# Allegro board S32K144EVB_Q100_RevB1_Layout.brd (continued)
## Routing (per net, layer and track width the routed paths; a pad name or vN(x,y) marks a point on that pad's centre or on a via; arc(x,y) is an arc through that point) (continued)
SDA_SWD_OE_B: length 19.5
  TOP w0.16: v1(25.27,37.82) 24.3,37.82 23.87,37.39 21.49,37.39 U8.20 ; v1(35.85,40.73) 35.59,41 35.59,41.44 R32.2
  BOTTOM w0.16: v1(25.27,37.82) 26.89,36.19 32.87,36.19 35.42,38.74 35.42,40.3 v1(35.85,40.73)
SDA_SWD_OE_B_R: length 3.5
  TOP w0.16: U9.3 35.64,40 35.79,40.15 R39.1 R32.1 v1(36.6,42.23)
SDA_SWD_OE_R: length 3.7
  TOP w0.16: U7.5 R30.2 R31.1 33.03,41.16 R35.2
SDA_USB_CONN_DN: length 13.3
  TOP w0.145: J7.2 4.65,43.37 4.83,43.55 7.56,43.55 7.94,43.17 7.94,43.11 ; 7.94,43.11 8.34,43.52 12.57,43.52 13.41,44.37 15.33,44.37 15.73,43.97 R25.1 ; 7.94,43.11 D19.2
SDA_USB_CONN_DP: length 13.6
  TOP w0.145: 7.92,44.3 7.92,44.29 8.39,43.82 12.44,43.82 13.29,44.66 15.45,44.66 15.94,44.18 R21.1 ; 7.92,44.3 7.46,43.85 4.85,43.85 4.67,44.02 J7.3 ; 7.92,44.3 D18.2
SDA_USB_DN: length 2.1
  TOP w0.145: U8.4 17.65,41.94 17.65,42.08 17.08,42.65 R25.2
SDA_USB_DP: length 2.1
  TOP w0.145: R21.2 17.25,42.9 17.29,42.86 17.29,42.86 17.84,42.31 17.99,42.31 U8.3
SDA_USB_P5V_SENSE: length 4.6
  TOP w0.16: U8.30 21.47,42.72 R20.1 22.79,44.04 22.79,44.04 R14.2 v1(23.98,45.22)
SDA_USBSHIELD: length 9.3
  TOP w0.16: 5.62,40.27 L2.1 6.21,40.76
  TOP w1.016: J7.9 J7.8 J7.10
SDA_VOUT33: length 6.4
  TOP w0.254: U8.5 16.91,41.97 15.71,41.97 C9.1
  TOP w0.508: J9.2 15.18,41.44 C9.1
SDA_XTAL: length 5.3
  TOP w0.16: Y1.1 23.41,35.3 23.41,35.71 C20.1 22.61,36.51 20.95,36.51 U8.18
SW1_RST_B: length 13.5
  TOP w0.16: SW5.4 SW5.2 11.15,53.63 v1(10.7,53.19) C1.1
  L3_MIX w0.16: v1(10.7,53.19) 10.7,51.72 11.65,50.77 11.65,49.19 J104.2
SWD_CLK_TGTMCU_BUF: length 21.8
  TOP w0.16: U10.4 29.91,37.62 v1(30.07,37.47) ; J8.1 42.68,43.86 v1(42.68,40.06)
  BOTTOM w0.16: v1(30.07,37.47) 32.95,37.47 34.74,39.26 34.74,40.32 35.61,41.19 37.17,41.19 38.3,40.06 v1(42.68,40.06)
SWD_DIO_TGTMCU_BUF: length 23.9
  TOP w0.16: U7.4 v1(30.02,40.66) ; U2.2 v1(30.44,47.35) 33.08,47.35 35.6,44.83 39.23,44.83 41.33,42.73 J106.1
  BOTTOM w0.16: v1(30.02,40.66) 30.78,40.66 32.05,41.94 32.05,45.74 v1(30.44,47.35)
TC_EXTAL_TP: length 2.2
  TOP w0.16: U8.10 16.39,38.34 16.09,38.34 15.72,37.97 TP11.1
TC_SDA_USB_ID_TP: length 2.2
  TOP w0.16: J7.4 5.88,44.67 TP6.1
TC_XTAL_TP: length 3
  TOP w0.16: TP10.1 15.83,38.85 16.19,38.85 U8.9
TP_2102_A: length 1.6
  TOP w0.16: U1.3 v1(7.74,53.46)
TP_2102_B: length 1.2
  TOP w0.16: U1.6 6.55,50.61 v1(6.24,50.29)
UART1_RX_TGTMCU_BUF: length 7
  TOP w0.16: U4.4 30.29,43.94 30.66,43.57 v1(32.75,43.57) 35.45,43.57 R24.1
UART1_RX_TGTMCU_R: length 8.8
  TOP w0.16: U8.25 22.89,40.6 23.67,40.6 23.88,40.39 25.35,40.39 v1(25.86,40.9) ; v1(27.02,43.73) 27.83,43.73 28.04,43.94 U4.3
  BOTTOM w0.16: v1(27.02,43.73) 27.02,42.06 v1(25.86,40.9)
UART1_TX_TGTMCU_BUF: length 6.4
  TOP w0.16: U2.1 v1(31.84,46.83) 32.26,46.83 R18.1
UART1_TX_TGTMCU_R: length 10.9
  TOP w0.16: U8.24 v1(23.29,40.08) ; v1(27.12,44.65) 27.65,45.18 27.65,47.12 27.88,47.35 U2.6
  BOTTOM w0.16: v1(23.29,40.08) 26.34,43.14 26.34,43.87 v1(27.12,44.65)
UART_RX: length 59
  TOP w0.16: R24.2 v1(34.07,43.05) ; R161.2 v1(84.66,44.35)
  BOTTOM w0.16: v1(34.07,43.05) 35.69,44.67 38.34,44.67 38.81,44.2 44.26,44.2 51.04,37.42 53.5,37.42 53.82,37.74 54.65,37.75 54.66,37.75 56.12,37.75 60.68,42.31 82.63,42.31 v1(84.66,44.35)
UART_TX: length 57.5
  TOP w0.16: v1(86.33,44.28) 86.33,43.34 R162.2 ; R18.2 v1(36.98,44.16)
  BOTTOM w0.16: v1(86.33,44.28) 83.79,41.74 67.09,41.74 66.65,41.29 66.22,41.29 65.86,41.65 60.5,41.65 56.26,37.42 54.8,37.42 54.8,37.41 53.96,37.4 53.64,37.08 50.42,37.08 43.94,43.56 37.58,43.56 v1(36.98,44.16)
V_TGTMCU: length 14.7
  TOP w0.254: 2.98,50.98 R2.2 2.47,50.47 ; U1.8 8.14,50 v1(8.55,49.59) ; U2.8 29.05,46.31 v1(29.34,46.01) U4.6 ; v1(30.05,38.7) 29.88,38.7 29.8,38.62 U10.6 ; 3.5,51.1 R4.1 2.99,50.59 ; 2.99,49.63 C4.1 ; U7.6 29.81,41.66 v1(30.04,41.89) ; C8.1 v1(30.09,42.77) ; 1.49,50.47 C2.1 0.98,50.98
  TOP w0.762: v1(38.48,42.57) v1(39.52,42.57) 39.52,39.41 38.86,38.76 SH1.1
  vias: v1(1.85,50.09) v1(2.77,50.09)
VREFH: length 16.2
  TOP w0.279: R99.2 63.08,31.47 64.89,29.66 U17.12
  TOP w0.508: R103.2 58.19,31.47 R99.2
  TOP w0.635: R109.1 D7.C 55.67,32.45 55.9,32.23 C148.1 v1(57.06,31.46) R103.2
VSUP: length 55.1
  TOP w0.254: U19.14 v1(15.66,18.74)
  TOP w0.381: Q1.3 32.88,18.84 ; Q1.3 32.88,18.44 ; Q1.3 32.88,18.24 ; Q1.3 32.08,18.14 ; Q1.3 31.68,18.19 ; Q1.3 32.88,18.64 ; C29.1 28.68,13.52 ; C29.1 27.72,13.14 ; C29.1 28.68,13.9 ; C29.1 28.04,13.14 ; C29.1 28.68,13.14 ; C29.1 28.68,14.29 ; D13.C 43.68,10.01 ; D13.C 42.08,11.61 ; D13.C 42.08,10.01 ; D13.C 42.88,10.01 ; D13.C 42.08,10.81 ; D13.C 43.68,11.61 ; D13.C 43.68,10.81 ; D13.C 42.88,11.61 ; Q1.2 32.08,17.86 ; Q1.2 32.88,17.37 ; Q1.2 32.88,17.77 ; Q1.2 32.08,16.87 ; Q1.2 31.68,16.92 ; Q1.2 32.88,16.97 ; D9.C 29.28,11.62 ; D9.C 27.68,12.42 ; D9.C 28.48,10.82 ; D9.C 29.28,12.42 ; D9.C 29.28,10.82 ; D9.C 28.48,12.42 ; D9.C 27.68,11.62 ; D9.C 27.68,10.82 ; 42.23,12.33 C128.1 ; C128.1 42.23,13.28 ; C128.1 42.87,12.33 ; C128.1 42.55,12.33 ; C128.1 42.23,14.23 ; C128.1 42.87,14.23 ; 34.92,17.78 C47.1 ; C47.1 35.68,18.42 ; C47.1 34.15,18.42 ; C47.1 34.15,17.78 ; C47.1 35.68,17.78 ; C47.1 34.54,17.78 ; 31.34,11.82 TP36.1 ; TP36.1 31.44,12.29 ; TP36.1 31.91,11.25 ; TP36.1 32.48,11.82 ; TP36.1 31.44,11.35 ; TP36.1 32.38,11.35 ; 31.68,15.65 Q1.1 ; Q1.1 32.08,15.6 ; Q1.1 32.88,16.5 ; Q1.1 32.88,15.7 ; Q1.1 32.08,16.59 ; Q1.1 32.88,16.1
  TOP w0.61: D6.A 20.63,23.5 21.29,24.16 U21.7
  TOP w0.635: v1(11.06,9.95) 11.06,9.67 10.42,9.04 R537.1 ; D6.A v3(17.99,23.5)
  vias: v1(28.11,12.79) v1(29.07,14.31) v1(29.09,13.6) v1(29.01,12.77)
VTRG_EN: length 4.6
  TOP w0.16: U11.3 v1(9.98,31.94) R70.2 R68.1 R69.2
VTRG_FAULT_B: length 16.3
  TOP w0.16: v1(20.38,43.64) 20.38,43.04 U8.32 ; v1(12.67,35.53) R60.2 11.22,35.53 U11.4
  BOTTOM w0.16: v1(12.67,35.53) 14.62,37.48 14.62,39.3 15.71,40.39 17.59,40.39 20.38,43.18 v1(20.38,43.64)
N20335552: length 5
  TOP w0.16: R119.1 47.85,42.36 48.38,41.83 J14.6
N20335572: length 2.5
  TOP w0.16: J14.8 R120.1
N20337946: length 53
  TOP w0.16: R166.2 73.48,14.93 v1(74.22,14.19) ; R165.2 v1(82.99,44.37)
  L3_MIX w0.16: v1(83.83,14.27) 83.83,17.51 83.36,17.97 83.36,35.15 82.66,35.86 82.66,44.05 v1(82.99,44.37) ; v1(74.22,14.19) 74.22,12.77 74.47,12.52 74.47,9.81 74.35,9.68 74.35,6.93 J5.3
  BOTTOM w0.16: v1(83.83,14.27) 83.26,14.84 74.88,14.84 v1(74.22,14.19)
N20338949: length 55.1
  TOP w0.16: R168.2 71.69,13.97 v1(71.22,13.5) ; R167.2 v1(81.31,44.27) ; J5.1 v1(71.69,5.12)
  L3_MIX w0.16: v1(71.22,13.5) 71.61,13.1 71.61,6.5 71.69,6.43 v1(71.69,5.12) ; v1(81.31,44.27) 81.92,43.66 81.92,35.2 82.32,34.8 82.32,18.13 82.16,17.98 v1(82.16,14.16)
  BOTTOM w0.16: v1(82.16,14.16) 81.83,14.48 76.37,14.48 75.61,13.72 71.91,13.72 71.68,13.5 v1(71.22,13.5)
N20340793: length 25.3
  TOP w0.16: SH13.1 95.15,32.61 95.43,32.9 v1(95.89,32.9)
  L3_MIX w0.16: J6.3 90.41,51.83 90.41,47.53 94.2,43.73 94.2,40.26 96.22,38.24 96.22,33.22 v1(95.89,32.9)
N20341657: length 96.4
  TOP w0.16: R133.1 88.69,16.31 v1(89.52,15.47) ; v1(66.52,13.96) R132.1
  L3_MIX w0.16: J1.13 48.22,48.78 48.73,48.27 48.73,28.39 45.85,25.51 45.85,23.58 46.98,22.45 46.98,17.73 45.95,16.7 45.95,9.17 v1(47.71,7.41)
  BOTTOM w0.16: v1(47.71,7.41) 49.41,9.11 54.05,9.11 54.61,9.66 54.9,9.66 59.2,13.96 v1(66.52,13.96) 70.79,13.96 72.3,15.47 v1(89.52,15.47)
N20341806: length 99.6
  TOP w0.16: R135.1 v1(62.15,13.37) ; v1(88.69,13.75) R134.1
  L3_MIX w0.16: v1(47.17,5.91) 47.17,6.91 44.79,9.29 44.79,14.56 44.67,14.69 44.67,16.29 45.76,17.39 45.76,23.19 45.51,23.44 45.51,25.65 46.29,26.42 46.29,29.03 46.2,29.12 46.2,30.53 48.36,32.68 48.36,48.16 47.47,49.05 47.47,51.59 J1.15
  BOTTOM w0.16: v1(47.17,5.91) 47.17,6.03 49.82,8.68 54.1,8.68 54.75,9.32 56.12,9.32 60.16,13.37 v1(62.15,13.37) 70.22,13.37 70.8,12.78 78.69,12.78 78.93,12.53 82.47,12.53 82.75,12.82 85.16,12.82 86.12,13.78 87.37,13.78 87.4,13.75 v1(88.69,13.75)
N20342040: length 84.1
  TOP w0.16: v1(28.92,50.71) 29.38,50.71 29.53,50.56 31.46,50.56 32.68,50.56 32.68,50.56 33.01,50.56 33.27,50.3 33.86,49.7 39.24,49.7 40.29,48.66 55.61,48.66 56.67,47.6 75.08,47.6 76.78,45.9 87.52,45.9 87.57,45.85 88.26,45.85 88.88,45.23 91.45,45.23 94.86,41.82 R567.1 94.86,40.55 94.85,40.54 R539.1
  BOTTOM w0.16: v1(28.92,50.71) 28.92,50.19 28.47,49.74 22.39,49.74 J2.19
N20342083: length 76.7
  TOP w0.16: v1(28.28,50.2) 32.85,50.2 33.69,49.36 39.1,49.36 40.17,48.3 55.46,48.3 56.5,47.26 74.91,47.26 76.61,45.57 86.59,45.57 86.64,45.51 87.84,45.51 90.22,43.12 90.22,41.83 90.16,41.76 R568.1 R540.1
  BOTTOM w0.16: J2.17 24.47,50.2 v1(28.28,50.2)
N20344687: length 67
  TOP w0.16: R146.1 77.18,14.31 76.12,13.25 v1(74.81,13.25) ; v1(93.32,37.24) R543.2 94.1,38.19 94.11,38.18 R541.2
  L3_MIX w0.16: v1(74.81,13.25) 74.81,12.66 74.81,12.66 74.81,9.67 74.81,9.66 v1(74.81,8.85) ; v1(93.32,37.24) 93.32,31.91 93.51,31.73 93.51,31.35 93.23,31.07 93.23,26.88 92.64,26.3 92.64,22.84 92.61,22.81 92.61,13.42 v1(92.73,13.29)
  BOTTOM w0.16: J4.11 64.31,5.97 64.31,6.32 66.84,8.85 70.04,8.85 70.1,8.91 70.74,8.91 70.81,8.85 v1(74.81,8.85) ; v1(92.73,13.29) 89.8,13.29 88.88,14.21 86.08,14.21 85.02,13.15 82.61,13.15 82.33,12.87 79.07,12.87 78.7,13.25 v1(74.81,13.25)
N20344693: length 67.5
  TOP w0.16: R147.1 88.69,23.01 89.15,22.55 89.27,22.55 90.36,21.46 v1(91.15,21.46) ; v1(90.09,36.98) R542.2 88.7,38.18 R544.2 ; J4.9 61.86,6.06 62.08,6.06 63.22,7.21 65.54,7.21 68.45,10.12 71.39,10.12 73.15,8.36 76.94,8.36 77.36,8.78 77.56,8.78 78.88,10.1 82.75,10.1 83.64,9.21 88.7,9.21 v1(91.15,11.67)
  L3_MIX w0.16: v1(91.15,11.67) v1(91.15,21.46) 90.82,21.79 90.82,21.83 90.69,21.96 90.69,22.66 90.14,23.22 90.14,24.52 90.23,24.61 90.23,28.54 89.7,29.07 89.7,35.24 90.51,36.06 90.51,36.42 90.09,36.84 v1(90.09,36.98)
N20408163: length 2.3
  TOP w0.16: U15.3 R170.2 34.12,32.71 R169.2
N20408770: length 1.6
  TOP w0.16: U15.4 40.06,32.71 40.06,32.71 C59.1
N20447644: length 70.3
  TOP w0.16: SH11.2 v1(94.4,36.71)
  L3_MIX w0.16: v1(62.14,26.25) 62.14,50.48 63.46,51.8 J1.1 ; v1(93.82,27.84) 93.82,30.25 94.18,30.61 94.18,32.01 94.08,32.11 94.08,36.38 v1(94.4,36.71)
  BOTTOM w0.16: v1(93.82,27.84) 76.86,27.84 75.58,26.56 64.27,26.56 64.25,26.57 62.46,26.57 v1(62.14,26.25)
N20447648: length 66.9
  TOP w0.16: v1(95.62,34.18) 95.16,34.18 95.15,34.19 SH12.2
  L3_MIX w0.16: v1(59.29,29.79) 59.29,51.75 J1.3 ; v1(95.62,34.18) 95.46,34.03 95.45,34.03 95.18,33.76 95.18,33.75 94.7,33.27 94.7,30.15 94.51,29.96 v1(94.51,29.5)
  BOTTOM w0.16: v1(94.51,29.5) 93.7,30.31 90.84,30.31 90.7,30.45 88.89,30.45 88.13,29.69 86.69,29.69 86.23,30.15 77.23,30.15 77.22,30.14 71.08,30.14 70.73,29.79 v1(59.29,29.79)
N20483325: length 50.2
  TOP w0.16: R81.1 60.01,25.42 58.68,24.09 52.06,24.09 v1(51.73,23.77)
  L3_MIX w0.16: v1(51.73,23.77) 50.81,22.84 50.81,18.13 51.24,17.69 51.28,17.69 52.2,16.77 52.2,16.39 50.26,14.44 v1(48.67,14.44)
  BOTTOM w0.16: J3.2 29.18,3.86 29.18,6.43 30.27,7.52 33.5,7.52 37.64,11.65 45.88,11.65 v1(48.67,14.44)
N20483330: length 48.3
  TOP w0.16: R90.1 v1(59.87,30.38)
  L3_MIX w0.16: v1(59.87,30.38) 59.87,24.57 55.76,20.47 v1(55.76,18.51)
  BOTTOM w0.16: v1(55.76,18.51) 54.17,18.51 52.41,16.75 52.41,16.37 51.42,15.38 50.83,15.38 46.16,10.71 37.61,10.71 33.45,6.55 32.64,6.55 31.71,5.62 31.71,3.85 J3.4
N20483362: length 70.4
  TOP w0.16: R545.1 v1(75.02,44.28)
  L3_MIX w0.16: v1(75.02,44.28) 73.91,43.17 73.91,38.89 73.41,38.39 73.41,38.01 75,36.42 75,34.98 74.17,34.15 74.17,19.21 73.44,18.48 73.44,18.06 73.49,18 73.49,12.77 v1(74.01,12.26)
  BOTTOM w0.16: v1(74.01,12.26) 64.85,12.26 61.78,9.19 59.46,9.19 58.61,8.34 49.96,8.34 47.63,6.02 47.63,5.38 46.05,3.79 44.35,3.79 J3.14
N20483368: length 57.5
  TOP w0.16: R546.1 v1(65.24,44.28)
  L3_MIX w0.16: v1(65.24,44.28) 65.24,35.71 63.48,33.95 63.48,16.59 63.94,16.14 63.94,11.34 61.15,8.55 v1(60.3,8.55)
  BOTTOM w0.16: J3.16 47.47,4.36 47.98,4.36 48.38,4.77 48.38,6.17 49.55,7.34 59.09,7.34 v1(60.3,8.55)
N20487643: length 4.3
  TOP w0.16: R533.2 C533.1 ; R533.2 v1(99.2,30.39) ; R533.2 R525.1
N20487701: length 2.6
  TOP w0.16: R527.1 SW8.1
N20487722: length 4.4
  TOP w0.16: v1(98.17,17.25) C535.1 R534.2 R528.1
N20498073: length 20.6
  TOP w0.16: Q1.4 v1(32.08,20.66) ; v1(14.9,18.24) U19.15
  BOTTOM w0.16: v1(32.08,20.66) 21.16,20.66 20.76,20.26 19.95,20.26 18.55,18.86 18,18.86 17.38,18.24 v1(14.9,18.24)
N20501046: length 23
  TOP w0.16: v1(9.65,12.44) R537.2 SW9.1 SW9.3 ; U19.12 v1(15.66,19.74)
  L3_MIX w0.16: v1(9.65,12.44) 9.65,12.9 9.74,12.99 9.74,19.34 10.25,19.85 15.09,19.85 15.2,19.74 v1(15.66,19.74)
N20514938: length 32.3
  TOP w0.203: 21.39,18.24 U19.6
  TOP w0.356: 21.39,18.24 22.14,18.98 R535.2
  TOP w0.381: R535.2 24.98,18.98 ; R535.2 24.98,19.62 ; R535.2 24.03,19.62 ; R535.2 23.08,19.62
  TOP w0.635: 25.46,18 Q1.5 ; Q1.5 28.05,15.62 ; Q1.5 25.46,20.38 ; Q1.5 28.05,20.39 ; Q1.5 30.64,20.38 ; Q1.5 30.64,15.63 ; Q1.5 30.64,18 ; Q1.5 25.46,15.63
  vias: v1(30.75,21.68)
N20519466: length 4.4
  TOP w0.16: C536.1 13.63,21.12 v1(14.21,20.54) 15.51,19.24 U19.13
N20529258: length 4.2
  TOP w0.61: R80.2 R171.2 D6.C
N20533540: length 2.6
  TOP w0.16: R172.1 SW7.1
N20579312: length 15.6
  TOP w0.508: v1(7.96,13.25) 7.96,14.26 C40.1 ; 7.96,24.04 v1(6.57,24.04)
  BOTTOM w0.508: v1(7.96,13.25) 7.96,22.64 v1(6.57,24.04)
N20579404: length 3.9
  TOP w0.305: R92.2 8.34,17.31 8.9,16.75 9.54,16.75 J109.2
N20579447: length 4.6
  TOP w0.305: J108.2 11.01,19.75 9.77,20.99 R98.2
N20615890: length 3.5
  TOP w0.16: R556.1 39.49,22.39 39.66,22.56 39.66,22.9 39.66,23.28 39.66,23.29 39.66,24.26 39.5,24.42 U26.5
N20616554: length 3.4
  TOP w0.16: R558.1 46.33,22.39 46.77,22.83 46.77,24.26 46.61,24.42 U28.5
N20618570: length 3.5
  TOP w0.16: R559.2 51.49,25.69 51.65,25.53 51.65,24.42 51.38,24.15 U29.5
N20622415: length 3.4
  TOP w0.16: R560.1 42.82,22.39 43.23,22.8 43.23,24.28 43.07,24.44 U30.5
N20627960: length 1.4
  TOP w0.16: R562.1 46.83,19.3 46.57,19.3 46.32,19.05 U32.5
N20628442: length 1.4
  TOP w0.16: R563.1 45.19,20.96 45.31,20.83 U32.7
N20629363: length 3.1
  TOP w0.16: U33.5 51.42,17.82 51.73,18.13 51.73,18.62 51.57,18.78 51.32,18.78 R564.2
N20629726: length 1.6
  TOP w0.16: U32.2 44.91,17.64 44.42,17.15 R565.2
N20631005: length 1.4
  TOP w0.16: U33.3 50.13,16.94 R566.2

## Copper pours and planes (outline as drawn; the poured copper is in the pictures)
GND on BOTTOM: 125.25,8.89 122.79,2.96 116.87,0.51 8.93,0.52 3,2.98 0.55,8.9 0.52,49.52 2.96,55.45 8.89,57.91 116.87,57.91 122.79,55.46 125.25,49.53 ; 51 cut-outs
P3V3 on TOP: 38.97,26.63 38.97,26.65 38.38,27.24 38.38,35.45 45.39,35.45 45.39,26.93 45.09,26.63
P3V3 on L3_MIX: 41.21,32.39 41.21,28.41 39.64,26.83 39.64,24.83 37.95,23.13 37.95,7.56 36.8,6.42 36.8,4.03 32.57,4.03 32.57,23.74
P3V3_SDA on TOP: 8.44,51.41 9.73,51.41 10.09,51.05 10.09,49.5 9.33,49.5 8.44,50.4
P3V3_SDA on TOP: 31.33,37.21 31.33,35.49 31.24,35.39 29.19,35.39 29.01,35.58 29.01,37.25 31.29,37.25
P3V3_SDA on BOTTOM: 29.6,36.74 29.6,37.88 30.45,38.74 33.13,38.74 34.22,39.82 34.22,40.4 35.4,41.58 37.86,41.58 37.86,42.89 34.29,42.89 31.36,39.96 28.92,39.96 28.87,40 28.87,42.35 31.09,42.35 31.38,42.64 31.38,43.4 30.42,44.36 30.42,44.43 30.44,44.44 30.44,45.69 29.03,45.69 26.89,47.83 22.35,47.83 18.16,52.02 7.52,52.02 6.75,52.79 4.78,52.79 4.72,52.73 4.72,51.49 5.95,50.25 9.39,50.25 10.59,49.05 10.59,27.64 11.78,26.45 18.7,26.45 19.42,27.16 19.42,28.39 14.57,28.39 14.57,33.88 16.92,36.23 16.92,38.23 16.44,38.23 16.27,38.06 16.27,36.67 13.58,33.98 13.58,31.39 12.24,31.39 11.86,31.77 11.86,35.72 13.48,37.34 13.48,43.84 14.48,44.84 16.84,44.84 19.22,42.46 19.85,43.08 19.85,44.32 17.24,46.93 17.24,48.9 19.44,48.9 21.68,46.66 24.62,46.66 26.22,45.07 28.25,45.07 28.25,42.82 27.57,42.13 27.57,40.1 27.09,39.62 27.09,38.53 27.28,38.34 28.05,38.34 28.3,38.09 28.3,37.32 28.88,36.74
P5V0 on TOP: 30.35,32.51 32.85,32.51 35,30.37 35,26.8 34.9,26.7 32.42,26.7 30.35,28.77
P5V0 on BOTTOM: 23.85,34.37 28.15,34.37 28.53,33.99 32.74,33.99 33.09,34.33 33.09,34.38 33.96,35.26 42.69,35.26 42.69,26.33 30.47,26.33 30.47,31.07 26.49,31.07 26.49,26.33 23.85,26.33
P5V0 on L3_MIX: 43.47,5.07 42.44,4.04 36.97,4.04 36.97,6.24 38.34,7.62 38.34,23.27 40.2,25.13 40.2,26.76 41.68,28.24 43.47,28.24
P5V_SBC on TOP: 33.22,25.92 33.22,21.45 36.37,21.45 37.02,20.79 41.54,20.79 41.84,21.09 41.84,22.49 40.92,23.42 40.15,23.42 39.5,22.77 37.89,22.77 37.89,25.92
P5V_SBC on BOTTOM: 42.31,20.13 42.31,16.91 44.58,16.91 44.58,19.37 43.91,20.04 43.91,21.15 44.03,21.26 45.57,21.26 46.59,20.25 46.59,19.53 47.69,18.43 49.39,18.43 49.76,18.79 49.76,23.76 49.73,23.76 49.73,24.37 49.2,24.9 48.65,24.9 47.19,23.44 38.5,23.44 38.5,23.51 38.24,23.77 35.89,23.77 35.89,26.14 30.3,26.14 30.3,30.89 26.69,30.89 26.69,22.87 31.94,22.87 33.3,21.5 37.65,21.5 38.22,20.93 41.42,20.93 41.42,20.94 41.5,20.94
P5V_SDA on TOP: 22.29,44.5 23.47,45.69 22.26,46.9 6.97,46.9 6.97,45.62 17.57,45.62 17.93,45.99 19.59,45.99 19.95,45.62 21.17,45.62
P5V_SDA on BOTTOM: 6.91,45.99 6.91,28.58 9.61,28.58 9.61,46.33 7.24,46.33
VBATT on TOP: 21.55,12.74 26.96,12.74 26.96,6.94 26.69,6.67 22.08,6.67 21.55,7.2
VDD on TOP: 45.77,38.45 51.32,38.45 52.51,39.64 54.85,39.64 54.85,38.09 54.84,38.08 54.84,36.22 48.7,36.22 48.7,25.93 45.76,25.93 45.76,35.84 39.81,35.84 39.81,38.45 40.38,39.02 45.2,39.02
VDD on TOP: 35.74,26.64 35.74,30.8 38.19,30.8 38.19,26.64
VDD on BOTTOM: 43.11,30.5 43.11,26.09 36.07,26.09 36.07,24.12 38.33,24.12 38.32,24.11 38.78,23.66 46.69,23.66 47.15,24.11 47.14,24.11 48.17,25.14 49.12,25.14 49.99,24.27 49.99,18.65 49.53,18.19 46.89,18.19 46.32,18.76 46.32,20.14 45.37,21.09 44.24,21.09 44.04,20.89 44.04,20.19 44.78,19.45 44.78,17.2 46.37,15.61 49.35,15.61 51.1,17.36 52.33,17.36 53.7,18.72 55.38,18.72 55.49,18.83 55.49,30.5
VDD on BOTTOM: 70.76,4.08 85.76,4.08 90.48,8.8 108.44,8.8 109.23,8.02 116.65,8.02 118.39,9.76 118.39,16.91 119.63,18.14 119.63,47.87 115.65,51.85 106.57,51.85 103.57,48.85 92,48.85 89.65,51.2 80.04,51.2 80.04,57.03 112.63,57.03 112.64,57.03 118.34,57.03 124.56,50.8 124.56,9.61 115.51,0.56 69.72,0.56 69.72,3.04
VDD on L3_MIX: 71.7,3.86 71.7,0.56 26.38,0.56 25.9,1.05 25.9,8.08 26.05,8.23 26.05,24.67 39.86,38.48 44.34,38.48 44.34,36.08 32.11,23.85 32.11,3.86 ; 1 cut-out
VDD_MCU on TOP: 58.07,41.96 58.07,34.46 56.85,34.46 56.85,32.09 62.99,32.09 65.08,30 68.83,30 69.15,29.68 75.6,29.68 75.6,31.21 69.22,31.21 68.82,30.81 65.75,30.81 64.6,31.97 64.6,33.35 61.36,33.35 59.92,34.78 59.92,41.96
VDD_MCU on L3_MIX: 75.31,42.76 75.31,34.93 74.55,34.18 74.55,19.62 74.88,19.3 74.88,17.74 75.8,17.74 75.8,22.26 75.6,22.46 75.6,33.29 76.25,33.94 76.25,42.76
(no net) on TOP: 8.9,0.52 2.98,2.97 0.53,8.89 0.52,40.98 0.84,40.98 0.84,42.44 0.52,42.44 0.52,45.61 0.84,45.61 0.84,47.07 0.52,47.07 0.52,49.54 2.97,55.46 8.89,57.91 116.87,57.91 122.79,55.46 125.25,49.53 125.25,8.89 122.79,2.96 116.87,0.51 ; 63 cut-outs
(no net) on L3_MIX: 125.25,8.89 122.79,2.96 116.87,0.51 8.9,0.52 2.99,2.98 0.55,8.9 0.52,49.54 2.97,55.46 8.89,57.91 116.87,57.91 122.79,55.46 125.25,49.53 ; 62 cut-outs
SDA_USBSHIELD on TOP (solid shape): 2.43,48.27 5.1,48.27 5.1,46.25 3.86,46.25 3.86,47.25 0.53,47.25 0.53,48.98 2.43,48.98
SDA_USBSHIELD on TOP (solid shape): 5.1,39.78 2.43,39.78 2.43,39.07 0.53,39.07 0.53,40.8 3.86,40.8 3.86,41.8 5.1,41.8
SDA_USBSHIELD on TOP: 5.01,39.78 6.6,39.78 6.6,40.84 6.59,40.85 4.97,40.85 4.93,40.81 4.93,39.86
V_TGTMCU on TOP: 0.83,51.31 3.57,51.31 3.77,51.11 3.77,49.76 3.45,49.43 1.64,49.43 0.83,50.24
V_TGTMCU on L3_MIX: 1.3,51.32 7.24,51.32 9.03,49.52 9.03,47.25 9.97,46.32 12.11,46.32 15.42,49.62 32.42,49.62 35.79,46.26 39.87,46.26 39.87,42.24 38.09,42.24 38.09,43.84 34.98,43.84 30.96,47.86 29.93,47.86 29.93,46.9 31.22,45.61 31.22,41.9 30.35,41.04 30.35,38.27 28.8,38.27 28.8,45.71 27.13,47.39 15.51,47.39 13.28,45.15 8.99,45.15 4.85,49.29 1.3,49.29
VSUP on TOP: 27.59,14.56 31.48,14.56 31.48,19.02 37.47,19.02 37.47,14.66 43.92,14.66 43.92,10.32 43.91,10.32 43.91,9.04 39.7,9.04 39.7,10.31 27.59,10.31
VSUP on BOTTOM: 18.66,24.27 18.66,21.95 16.1,21.95 16.1,18.52 13.8,18.52 13.8,14.56 29.35,14.56 29.35,12 13.33,12 12.39,11.06 12.39,9.6 10.85,9.6 10.73,9.72 10.73,12.4 11.88,13.56 11.88,24.27 ; 1 cut-out
N20514938 on TOP: 30.99,15.3 30.99,21.83 22.24,21.83 22.24,18.48 25.06,18.48 25.06,15.3

Small or netless copper shapes (teardrops, artwork), in the pictures only: 1 on L2_GND

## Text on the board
BOTTOM: 170-29248 REV B1 | 7 OF 10 | SECONDARY SIDE
Board Geometry/Soldermask Bottom: 8 OF 10 | SECONDARY SOLDERMASK
Ref Des/Silkscreen Bottom: GND | LIN | VBAT | CAN_HI | CAN_LO | VDD | E10/A3 | NC | E11/A2 | A14 | AREF | E7 | C13 | B2 | C12 | B3 | E8 | B4 | B5 | D0 | D16 | D14 | B6 | VIN | D15 | D13 | IOREF | B7 | E0 | RESET | 3.3V | E9 | 5V | C5 | C4 | A10 | A4 | E8/C11 | D4 | C7 | E3 | C3/C10 | B12 | D3 | C6 | B0 | B11 | D5 | B17 | B1 | B10 | D12 | B14 | A6/E11/A2 | B9 | D11 | B15 | D10 | C0/E10/A3 | B8 | B16 | E2 | A3 | A17 | C14 | A11 | E6 | A2 | C3 | E4 | A9 | A8 | E5 | E12 | A12 | A13 | D17 | C9 | C8 | E16 | A15/D11 | C16 | D8 | E15 | A16/D10 | C17 | D9 | E14 | A1 | D2 | E13 | A0 | D1 | A7 | B13 | E1 | C1 | D7 | C2 | D6 | C15 | OpenSDA | 9 OF 10 | SECONDARY SILKSCREEN
User.Comments: 1 OF 1 | TEST PROBE | 1/1 | 1
TOP: 4 OF 10 | PRIMARY SIDE
Board Geometry/Soldermask Top: 3 OF 10 | PRIMARY SOLDERMASK
Ref Des/Silkscreen Top: GND | SBC_IO | VSUP | LIN | RESET | # | P5V0 | SBC_SCK | SBC_MISO | SBC_CAN_RX | SBC_MOSI | SBC_CAN_TX | SBC_CS | ## | SWD_CLK | SWD_DIO | VDD | P3V3 | MCU | * | POT | B | G | R | CAN | LO | HI | SDA | PWR IN (5-12V) | SWD | ** | TOUCH ELECTRODES | 2 OF 10 | PRIMARY SILKSCREEN | S32K144EVB-Q100
L2_GND: 5 OF 10 | GROUND PLANE
L3_MIX: 6 OF 10 | MIXED SIGNAL
DIMENSION: PRIMARY DATUM | GRID ORIGIN
BODY_CENTER: 22. | INTENTIONAL SHORT (8) ON: | Location           RefDes      Net 1                     Net 2 | (113.50 1329.90)   J9        P3V3_SDA               &  SDA_VOUT33 | (299.72 1681.10)   J105      SDA_RST_TGTMCU_J_B     &  SDA_RST_TGTMCU_B | (1213.10 1300.30)  SH1       V_TGTMCU               &  VDD | (1278.70 1578.40)  J8        SWD_CLK_TGTMCU_BUF     &  JTAG_TCLK/SWD_CLK | (1278.70 1442.70)  J106      SWD_DIO_TGTMCU_BUF     &  JTAG_TMS/SWD_DIO_PTA4 | (3336.22 1082.50)  SH13      N20340793              &  PTD2 | (3336.70 1202.70)  SH11      PTA2                   &  N20447644 | (3336.71 1144.40)  SH12      PTA3                   &  N20447648 | 17 | X4 | 16 | 8
PASTEMASK_TOP: 1 OF 10 | PASTEMASK TOP
User.5: 10 OF 10 | SECONDARY PASTEMASK
User.14: 09-01-16 | 12-19-16 | O.R. | B | B1 | RE-SPIN PER ECO66785 | CHANGED THE SAMTEC TO JTX
User.20: FIGURE | SIZE | 8.0 | 10.0 | 14.0 | 15.0 | 28.0 | 31.0 | 40.0 | 44.0 | 45.0 | 100.0 | 125.0 | 34.0x26.0 | 60.0x33.0 | 111.0x32.0 | 122.0x32.0 | DRILL CHART: TOP to BOTTOM | ALL UNITS ARE IN MILS | TOLERANCE | +0.0/-8.0 | +0.0/-10.0 | +2.0/-2.0 | +3.0/-3.0 | PLATED | NON-PLATED | QTY | 359 | 518 | 28 | 2 | 3 | 20 | 133 | 6 | 9 | 1 | 4
